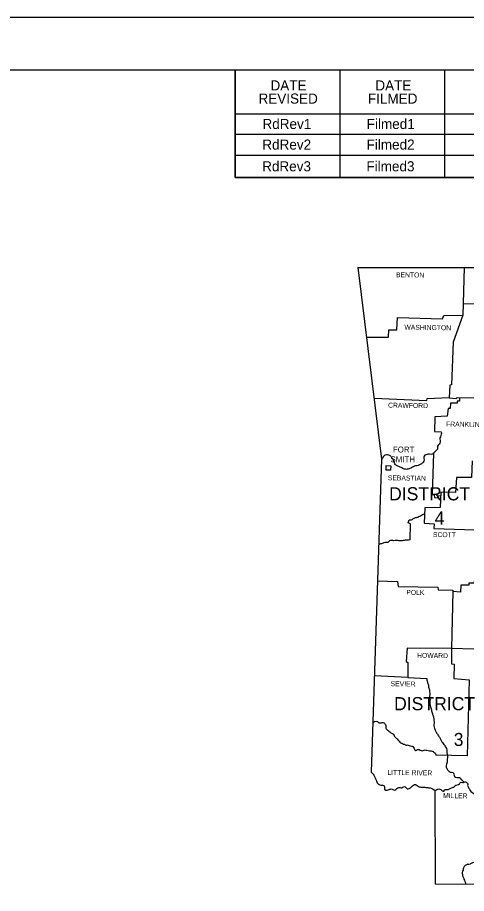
# Model space of a CAD drawing. Extents: x -0.25 to 1.42, y 0 to 0.92.
# Drawn here: x 0.9604 to 1.1381, y 0.5701 to 0.9167 of the extents above; entities that cross this region are included whole.
import ezdxf

# ---------------------------------------------------------------- set-up
doc = ezdxf.new("R2010")
doc.units = 0
for name, color, linetype in [('SHET_Annotations', 7, 'Continuous'), ('SHET_Border-Lines', 7, 'Continuous'), ('SHET_Border-Text', 7, 'Continuous')]:
    doc.layers.add(name, color=color, linetype=linetype)

msp = doc.modelspace()

# ---------------------------------------------------------------- linework, layer by layer
at = {"layer": 'SHET_Annotations'}
for p, q in [((1.10377, 0.70837), (1.10343, 0.70833)), ((1.10185, 0.63817), (1.10109, 0.63769))]:
    msp.add_line(p, q, dxfattribs=at)
for points in [[(1.09511, 0.81784), (1.16886, 0.81779), (1.23365, 0.81792), (1.31002, 0.81909), (1.34545, 0.81992)], [(1.09511, 0.81784), (1.10455, 0.74198), (1.10045, 0.61817)], [(1.1372, 0.81781), (1.13672, 0.79894)], [(1.13684, 0.80359), (1.14835, 0.80321), (1.14861, 0.80176), (1.15019, 0.80171), (1.15014, 0.80083), (1.1512, 0.80054), (1.1513, 0.79554), (1.15273, 0.79523), (1.15283, 0.79325), (1.15481, 0.793), (1.15491, 0.79115), (1.15886, 0.79073), (1.16912, 0.791), (1.1692, 0.81779)], [(1.09854, 0.79022), (1.10724, 0.79019), (1.10745, 0.79318), (1.11059, 0.79318), (1.11087, 0.79805), (1.12869, 0.79743), (1.12921, 0.79878), (1.13672, 0.79894), (1.13289, 0.78825), (1.13214, 0.77131), (1.13159, 0.77129), (1.13134, 0.76618), (1.13401, 0.76595), (1.13442, 0.76636), (1.15618, 0.76595), (1.15641, 0.76353)], [(1.10154, 0.76614), (1.12247, 0.76514), (1.12257, 0.76589), (1.13134, 0.76629)], [(1.13537, 0.76634), (1.13533, 0.76493), (1.13447, 0.76493), (1.1345, 0.7641), (1.13175, 0.76405), (1.1317, 0.76203), (1.13092, 0.76203), (1.13048, 0.75897), (1.12555, 0.75871), (1.12553, 0.75295), (1.12817, 0.75275)], [(1.12508, 0.74427), (1.12459, 0.728), (1.12532, 0.72782), (1.12542, 0.72673), (1.12682, 0.72666), (1.12693, 0.72741), (1.12792, 0.72757)], [(1.14041, 0.74123), (1.1401, 0.73472), (1.13416, 0.73467), (1.13382, 0.72873), (1.12796, 0.72889), (1.12778, 0.72279), (1.12161, 0.72271), (1.1214, 0.71659), (1.12532, 0.71639), (1.12516, 0.71449), (1.14558, 0.71393)], [(1.17039, 0.73425), (1.17018, 0.72769), (1.15981, 0.72764), (1.15844, 0.72647), (1.15763, 0.72466), (1.15652, 0.72471), (1.15647, 0.7237), (1.15514, 0.72354), (1.15519, 0.72261), (1.14858, 0.72277), (1.14832, 0.72204), (1.1456, 0.72194), (1.14552, 0.69525), (1.14321, 0.6952), (1.14342, 0.69385), (1.14122, 0.69387), (1.14116, 0.69286), (1.13901, 0.69286), (1.13906, 0.69216), (1.1359, 0.69206), (1.13582, 0.68928), (1.13274, 0.68957), (1.13222, 0.66711)], [(1.11588, 0.70998), (1.11603, 0.71641), (1.1151, 0.71672), (1.11541, 0.71794)], [(1.10295, 0.69382), (1.11082, 0.69356), (1.11103, 0.69164), (1.1268, 0.69131), (1.12698, 0.69032), (1.13274, 0.69014), (1.13274, 0.68957)], [(1.15867, 0.6662), (1.13222, 0.66711), (1.11466, 0.66714), (1.11427, 0.66192), (1.11489, 0.66148), (1.11487, 0.65562), (1.10171, 0.65622)], [(1.13222, 0.66711), (1.13222, 0.66104), (1.13323, 0.66086), (1.13312, 0.65521), (1.13919, 0.65471), (1.13844, 0.62458), (1.12604, 0.62486)], [(1.11487, 0.65562), (1.12241, 0.65521)], [(1.12566, 0.61083), (1.12576, 0.5739), (1.29301, 0.57362)]]:
    msp.add_lwpolyline(points, dxfattribs=at)
msp.add_lwpolyline([(1.10628, 0.73763), (1.10633, 0.73939), (1.10815, 0.73934), (1.1081, 0.73757)], close=True, dxfattribs=at)
for points in [[(1.12817, 0.75275), (1.12817, 0.75179), (1.12781, 0.7508), (1.12757, 0.74992), (1.12773, 0.74878), (1.12732, 0.74787), (1.12672, 0.74712), (1.12672, 0.74624), (1.12604, 0.74528), (1.12529, 0.74452), (1.12467, 0.74395), (1.1235, 0.74388), (1.12254, 0.74382), (1.12161, 0.74349), (1.12125, 0.74279), (1.1214, 0.74175), (1.12104, 0.74074), (1.12011, 0.73999), (1.11904, 0.73947), (1.11795, 0.73929), (1.11642, 0.73856), (1.11507, 0.73799), (1.1136, 0.73804), (1.11225, 0.73864), (1.111, 0.73918), (1.11004, 0.73975), (1.10929, 0.74141), (1.10877, 0.74235), (1.10789, 0.74328), (1.10688, 0.74364), (1.106, 0.74354), (1.10455, 0.74198)], [(1.11541, 0.71794), (1.1164, 0.71802), (1.11736, 0.71864), (1.11863, 0.71895), (1.11992, 0.7196), (1.12153, 0.72037)], [(1.11588, 0.70998), (1.11458, 0.70995), (1.11305, 0.70977), (1.11168, 0.70959), (1.11046, 0.70982), (1.10934, 0.70964), (1.10856, 0.70982), (1.10761, 0.70959), (1.10703, 0.70902), (1.10589, 0.70902), (1.10509, 0.70866), (1.10377, 0.70837)], [(1.12241, 0.65521), (1.12265, 0.65383), (1.12306, 0.65261), (1.12309, 0.65173), (1.12353, 0.65036), (1.1235, 0.64986), (1.12366, 0.64883), (1.12348, 0.64831), (1.12368, 0.64722), (1.12366, 0.64636), (1.12363, 0.64569), (1.12371, 0.64455), (1.12405, 0.64354), (1.12441, 0.64206), (1.12464, 0.64125), (1.12503, 0.64006), (1.12524, 0.63861), (1.12529, 0.63755), (1.12521, 0.63653), (1.1255, 0.63539), (1.12599, 0.63425), (1.12662, 0.63316), (1.12739, 0.63192), (1.12794, 0.63093), (1.12861, 0.62989), (1.12916, 0.62904), (1.13001, 0.62792), (1.13038, 0.62702), (1.13038, 0.62577), (1.13056, 0.62455), (1.13051, 0.62326), (1.13043, 0.62204), (1.13009, 0.62043), (1.1303, 0.61965), (1.13118, 0.61851), (1.13172, 0.61817), (1.13268, 0.61799), (1.13312, 0.61734), (1.13341, 0.61641), (1.13437, 0.61607), (1.13543, 0.61599), (1.13595, 0.61542), (1.13663, 0.6147), (1.13704, 0.61409)], [(1.10185, 0.63817), (1.10286, 0.63819), (1.10351, 0.6376), (1.10395, 0.63765), (1.10465, 0.63775), (1.10538, 0.6377), (1.10584, 0.63729), (1.10626, 0.63659), (1.10623, 0.63589), (1.10626, 0.6356), (1.10659, 0.63503), (1.10714, 0.63456), (1.10774, 0.63412), (1.10825, 0.63373), (1.10919, 0.63316), (1.10929, 0.63298), (1.10963, 0.63223), (1.1101, 0.63166), (1.11064, 0.63127), (1.11124, 0.63065), (1.1115, 0.63036), (1.11196, 0.62971), (1.11246, 0.62966), (1.11318, 0.62925), (1.11367, 0.62912), (1.11419, 0.62878), (1.11474, 0.62896), (1.11544, 0.62865), (1.11635, 0.62842), (1.11686, 0.62829), (1.11743, 0.62743), (1.11806, 0.6267), (1.11876, 0.62712), (1.12016, 0.6267), (1.12101, 0.62668), (1.12179, 0.62691), (1.12239, 0.62683), (1.12348, 0.62658), (1.12415, 0.62658), (1.1249, 0.62632), (1.12558, 0.62577), (1.12602, 0.62515), (1.12604, 0.62486)], [(1.10045, 0.61817), (1.10174, 0.61646), (1.10229, 0.61519), (1.10309, 0.61361), (1.10421, 0.61299), (1.10553, 0.61273), (1.10579, 0.6112), (1.10716, 0.61114), (1.10828, 0.61148), (1.10978, 0.61107), (1.11139, 0.61213), (1.1123, 0.6119), (1.1136, 0.61244), (1.11463, 0.61159), (1.11637, 0.61234), (1.1179, 0.61332), (1.11935, 0.61239), (1.12078, 0.61226), (1.12247, 0.61203), (1.12379, 0.61192), (1.12498, 0.61135), (1.12566, 0.61083)], [(1.12566, 0.61083), (1.12724, 0.61151), (1.12796, 0.6113), (1.12853, 0.6107), (1.12923, 0.61068), (1.1296, 0.61122), (1.13027, 0.6113), (1.13082, 0.61125), (1.13141, 0.61159), (1.13191, 0.61182), (1.13258, 0.61205), (1.1331, 0.61226), (1.13354, 0.61275), (1.1344, 0.61314), (1.13533, 0.61348), (1.13559, 0.61395), (1.13606, 0.61413), (1.13696, 0.61407), (1.13759, 0.61433), (1.13808, 0.6141), (1.13852, 0.61379), (1.13862, 0.61262), (1.13899, 0.61197), (1.13956, 0.61083), (1.14031, 0.61024), (1.14103, 0.60964), (1.14129, 0.60928), (1.1421, 0.60858), (1.14277, 0.60837), (1.14308, 0.60788), (1.14358, 0.60666), (1.14433, 0.60565)], [(1.14433, 0.60565), (1.14407, 0.6043), (1.14399, 0.60323), (1.14422, 0.60204), (1.14399, 0.60142), (1.14435, 0.60056), (1.14505, 0.59989), (1.14555, 0.59916), (1.14586, 0.59807), (1.14547, 0.59691), (1.14591, 0.59569), (1.14633, 0.59522), (1.14658, 0.59447), (1.14622, 0.59309), (1.14583, 0.59203), (1.14492, 0.59099), (1.14467, 0.59047), (1.1448, 0.5898), (1.14503, 0.58871), (1.14477, 0.58837), (1.1442, 0.5876), (1.14399, 0.58674), (1.14358, 0.58599), (1.14316, 0.58469), (1.14256, 0.58358), (1.14246, 0.58233), (1.14153, 0.58236), (1.14052, 0.58233), (1.13953, 0.58168), (1.13867, 0.58163), (1.13761, 0.58119), (1.13696, 0.58033), (1.13676, 0.57937), (1.13647, 0.57847), (1.13673, 0.57691), (1.13714, 0.57582), (1.13748, 0.57494), (1.13792, 0.57388)]]:
    msp.add_spline(points, degree=3, dxfattribs=at)
at = {"layer": 'SHET_Border-Lines'}
for p, q in [((1.04658, 0.85338), (1.04658, 0.89583)), ((1.0881, 0.85338), (1.0881, 0.89583)), ((1.12962, 0.85338), (1.12962, 0.89583)), ((1.04658, 0.87856), (1.21266, 0.87856)), ((1.04658, 0.87057), (1.21266, 0.87057)), ((1.04658, 0.86223), (1.21266, 0.86223)), ((1.21266, 0.85338), (1.04658, 0.85338))]:
    msp.add_line(p, q, dxfattribs=at)
for points in [[(0, 0), (1.41667, 0), (1.41667, 0.91667), (0, 0.91667)], [(0.02083, 0.02083), (1.39583, 0.02083), (1.39583, 0.89583), (0.02083, 0.89583)], [(1.04658, 0.85338), (1.21266, 0.85338), (1.21266, 0.84075), (1.39583, 0.84075), (1.39583, 0.89583), (1.04658, 0.89583)]]:
    msp.add_lwpolyline(points, close=True, dxfattribs=at)

# ---------------------------------------------------------------- texts
at = {"layer": 'SHET_Annotations'}
for s, height, p in [('RdRev1', 0.004, (1.05737, 0.87256)), ('Filmed1', 0.004, (1.09864, 0.87256)), ('RdRev2', 0.004, (1.0573, 0.8644)), ('Filmed2', 0.004, (1.09858, 0.8644)), ('RdRev3', 0.004, (1.05725, 0.85581)), ('Filmed3', 0.004, (1.09853, 0.85581)), ('FORT', 0.002334, (1.10901, 0.7446)), ('SMITH', 0.002334, (1.10805, 0.74074)), ('DISTRICT', 0.005203, (1.10749, 0.72565)), ('4', 0.0052, (1.12553, 0.71607)), ('DISTRICT', 0.005203, (1.10947, 0.64263)), ('3', 0.00516, (1.13311, 0.62849))]:
    msp.add_text(s, height=height, dxfattribs=at).set_placement(p)
for s, height, rotation, p in [('BENTON', 0.001945, 359.2874, (1.11022, 0.81395)), ('WASHINGTON', 0.001945, 359.2079, (1.11354, 0.7932)), ('CRAWFORD', 0.001945, 359.2748, (1.10709, 0.76234)), ('FRANKLIN', 0.001945, 359.1782, (1.13006, 0.7549)), ('SEBASTIAN', 0.001945, 359.1959, (1.10699, 0.73361)), ('SCOTT', 0.001945, 359.32, (1.12485, 0.71117)), ('POLK', 0.001945, 359.3233, (1.11431, 0.6883)), ('HOWARD', 0.001945, 359.303, (1.11858, 0.66338)), ('SEVIER', 0.001945, 359.1815, (1.10811, 0.65215)), ('LITTLE RIVER', 0.0019451, 359.2076, (1.10681, 0.61708)), ('MILLER', 0.001945, 359.1885, (1.12886, 0.60791))]:
    msp.add_text(s, height=height, rotation=rotation, dxfattribs=at).set_placement(p)
at = {"layer": 'SHET_Border-Text'}
for s, p in [('DATE', (1.06054, 0.8878)), ('DATE', (1.10206, 0.8878)), ('REVISED', (1.0558, 0.8826)), ('FILMED', (1.09912, 0.8826))]:
    msp.add_text(s, height=0.004, dxfattribs=at).set_placement(p)

doc.saveas('drawing.dxf')
